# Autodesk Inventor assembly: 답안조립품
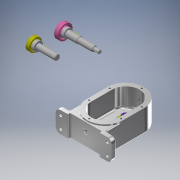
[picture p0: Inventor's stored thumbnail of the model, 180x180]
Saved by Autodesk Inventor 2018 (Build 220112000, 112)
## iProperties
Created: 2021-05
Part Number: 답안조립품
Material: 일반
Document SubType Name: Assembly
Designer: Admin
Author: Admin
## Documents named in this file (11)
- C:\Users\Admin\Desktop\710509V1007\답안조립품.iam
- C:\Users\Admin\Desktop\710509V1007\본체.ipt
- C:\Users\Admin\Desktop\710509V1007\부품\축 A.ipt
- C:\Users\Admin\Desktop\710509V1007\부품\축 B.ipt
- C:\Users\Admin\Desktop\710509V1007\부품\베어링 6001.ipt
- 베어링 6001.ipt
- C:\Users\Admin\Desktop\710509V1007\부품\베어링 6002.ipt
- 베어링 6002.ipt
- C:\Users\Admin\Desktop\710509V1007\부품\칼라.ipt
- C:\Users\Admin\Desktop\710509V1007\부품\키 5 x 5 x 12.ipt
- C:\Users\Admin\Desktop\710509V1007\부품\키 4 x 4 x 12.ipt
